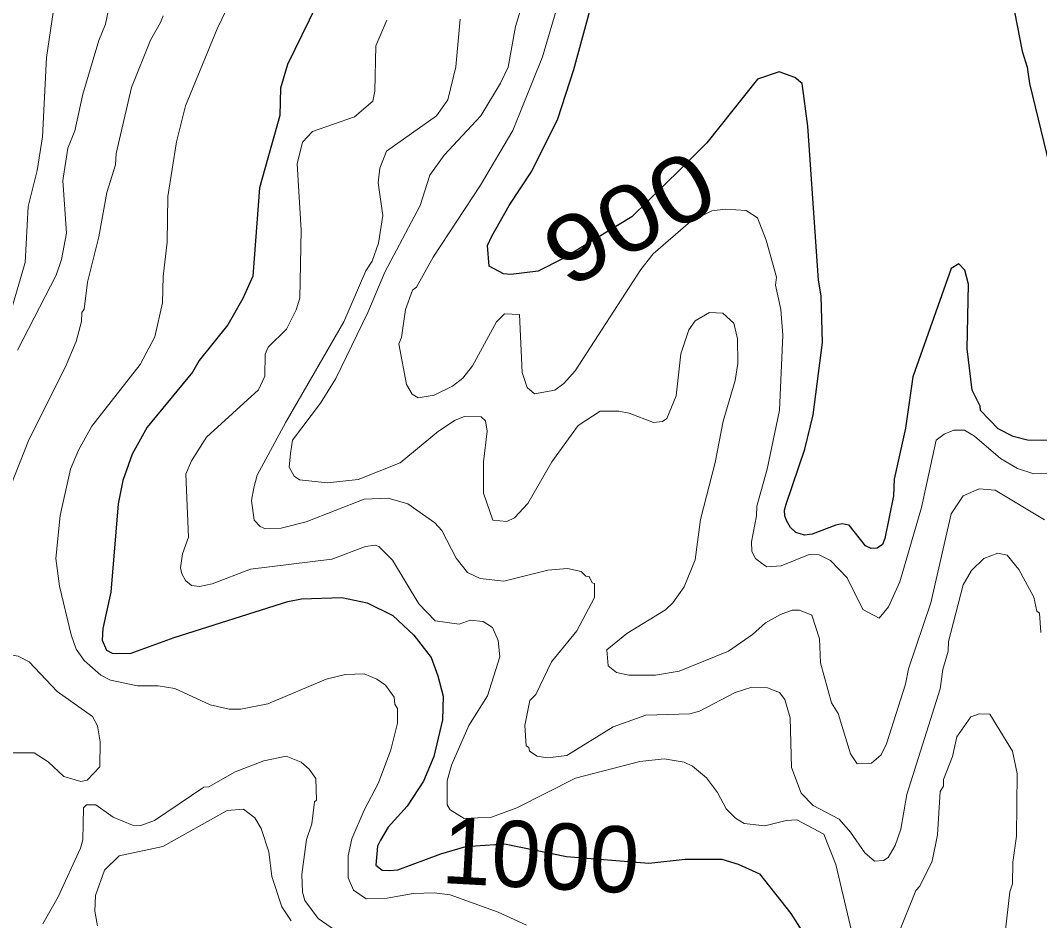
# Model space of a CAD drawing. Extents: x 598.3 to 623.2, y 6902.2 to 6930.1.
# Drawn here: x 611.773 to 613.004, y 6927.507 to 6928.595 of the extents above; entities that cross this region are included whole.
import ezdxf
from ezdxf.enums import TextEntityAlignment as Align

# ---------------------------------------------------------------- set-up
doc = ezdxf.new("R2010")
doc.units = 0
doc.header["$LTSCALE"] = 0.032
doc.layers.add('1', color=7, linetype='Continuous', lineweight=25)
doc.layers.add('2', color=7, linetype='Continuous', lineweight=13)
doc.layers.add('61', color=7, linetype='Continuous')

msp = doc.modelspace()

# ---------------------------------------------------------------- linework, layer by layer
at = {"layer": '1'}
for points in [[(613.0078, 6928.8607), (612.9766, 6928.8623), (612.9569, 6928.8518), (612.9422, 6928.8277), (612.9391, 6928.7936), (612.9472, 6928.7163), (612.9675, 6928.6366), (612.9828, 6928.5576), (612.9892, 6928.5385), (612.9917, 6928.5188), (613.0161, 6928.419)], [(612.1387, 6928.6312), (612.0954, 6928.5415), (612.0867, 6928.5129), (612.0858, 6928.4799), (612.0615, 6928.3925), (612.0534, 6928.2859), (612.0414, 6928.2587), (612.0231, 6928.227), (611.9886, 6928.1837), (611.9806, 6928.1695), (611.9257, 6928.1033), (611.9077, 6928.0706), (611.8961, 6928.0387), (611.8907, 6928.0104), (611.8818, 6927.9036), (611.8721, 6927.8598), (611.8714, 6927.8457), (611.8767, 6927.8338), (611.8833, 6927.8302), (611.9053, 6927.8295), (611.9582, 6927.8489), (612.0958, 6927.8926), (612.112, 6927.8958), (612.161, 6927.8973), (612.1914, 6927.8908)], [(612.8005, 6927.9565), (612.7936, 6927.9598), (612.7739, 6927.9847), (612.7651, 6927.9864), (612.7578, 6927.9848), (612.7294, 6927.9738), (612.7199, 6927.9728), (612.7095, 6927.976), (612.703, 6927.9821), (612.6981, 6927.9903), (612.6963, 6927.9961), (612.6958, 6928.0027), (612.6977, 6928.0102), (612.7202, 6928.0764), (612.7303, 6928.1179), (612.7416, 6928.2057), (612.7399, 6928.262), (612.7367, 6928.2808), (612.7238, 6928.467), (612.7173, 6928.5185), (612.7082, 6928.526), (612.6894, 6928.5327), (612.663, 6928.5238), (612.602, 6928.4468), (612.5707, 6928.4155), (612.5115, 6928.3576), (612.4274, 6928.3066), (612.3983, 6928.2917), (612.365, 6928.2876), (612.3564, 6928.2887), (612.3388, 6928.2978), (612.3368, 6928.3229), (612.3423, 6928.3342), (612.3631, 6928.3711), (612.3904, 6928.4125), (612.4221, 6928.4761), (612.4413, 6928.5356), (612.4641, 6928.6201)], [(613.0284, 6928.0869), (612.9895, 6928.0876), (612.9722, 6928.0919), (612.9539, 6928.1013), (612.9326, 6928.1235), (612.9322, 6928.1287), (612.9227, 6928.1479), (612.9164, 6928.1978), (612.918, 6928.2762), (612.9138, 6928.2929), (612.9066, 6928.3007), (612.8971, 6928.2949), (612.8508, 6928.1642), (612.8421, 6928.1021), (612.8282, 6928.0402), (612.8273, 6928.0201), (612.8171, 6927.9686), (612.8142, 6927.9614), (612.8077, 6927.9569), (612.8005, 6927.9565)], [(612.1914, 6927.8908), (612.2224, 6927.8757), (612.2479, 6927.8518), (612.269, 6927.8248), (612.2768, 6927.8025), (612.2833, 6927.7779), (612.2826, 6927.7496), (612.2721, 6927.705), (612.2596, 6927.6752), (612.2398, 6927.6451), (612.2168, 6927.6195), (612.2076, 6927.6041), (612.204, 6927.5965), (612.202, 6927.5736), (612.2096, 6927.5676), (612.2187, 6927.5672), (612.2285, 6927.5679), (612.2804, 6927.5874), (612.3109, 6927.5962), (612.3575, 6927.5995), (612.4323, 6927.5841), (612.532, 6927.5763), (612.5757, 6927.5809), (612.6201, 6927.5809), (612.6398, 6927.5751), (612.6654, 6927.5631), (612.7034, 6927.5153), (612.7188, 6927.491)]]:
    msp.add_lwpolyline(points, dxfattribs=at)
at = {"layer": '2'}
for points in [[(611.9217, 6928.8125), (611.8753, 6928.5904), (611.8671, 6928.5704), (611.8478, 6928.5058), (611.8383, 6928.4614), (611.8298, 6928.4405), (611.8236, 6928.4015), (611.8284, 6928.3378), (611.822, 6928.3057), (611.8158, 6928.2869), (611.7691, 6928.1963)], [(611.7602, 6928.2401), (611.7782, 6928.3021), (611.7819, 6928.3701), (611.7927, 6928.4133), (611.7992, 6928.4541), (611.8042, 6928.5501), (611.8155, 6928.6265), (611.8187, 6928.6309), (611.8188, 6928.6408), (611.8494, 6928.7685), (611.8528, 6928.7962)], [(612.4113, 6928.7208), (612.3708, 6928.5874), (612.3618, 6928.5385), (612.3528, 6928.5189), (612.329, 6928.4797), (612.2845, 6928.4321), (612.2672, 6928.408), (612.2556, 6928.3712), (612.2128, 6928.2906), (612.1924, 6928.2417), (612.1535, 6928.1622), (612.1352, 6928.1322), (612.1013, 6928.0875), (612.0989, 6928.0712), (612.0972, 6928.0547), (612.1035, 6928.0439), (612.1097, 6928.0397), (612.1435, 6928.0359), (612.1808, 6928.04), (612.2313, 6928.06), (612.2777, 6928.0984), (612.2977, 6928.1118), (612.3093, 6928.1159), (612.3294, 6928.1158), (612.3344, 6928.1109), (612.3367, 6928.0984), (612.3321, 6928.0614), (612.3321, 6928.0233), (612.3434, 6927.9907), (612.3602, 6927.989), (612.3697, 6927.9934), (612.3857, 6928.011), (612.4146, 6928.0612), (612.4466, 6928.1052), (612.4731, 6928.1224), (612.4955, 6928.1225), (612.5079, 6928.1201), (612.5375, 6928.1087)], [(612.384, 6927.5014), (612.35, 6927.5168), (612.292, 6927.538), (612.2726, 6927.5404), (612.2472, 6927.5396), (612.2156, 6927.534), (612.1903, 6927.5332), (612.1751, 6927.5436), (612.1685, 6927.5585), (612.1685, 6927.5852), (612.1731, 6927.6054), (612.188, 6927.6403), (612.2054, 6927.6734), (612.2203, 6927.7131), (612.2283, 6927.7453), (612.2283, 6927.763), (612.2251, 6927.7682), (612.2242, 6927.777), (612.2135, 6927.7913), (612.2034, 6927.7985), (612.1878, 6927.8051), (612.1655, 6927.8044), (612.1419, 6927.7984), (612.0716, 6927.7687), (612.039, 6927.7624), (612.0249, 6927.7624), (612.0017, 6927.7677), (611.9593, 6927.7874), (611.9391, 6927.7905), (611.9141, 6927.7907), (611.8812, 6927.7973), (611.8696, 6927.8033), (611.8495, 6927.8212), (611.8399, 6927.8348), (611.8337, 6927.852), (611.8197, 6927.9109), (611.8155, 6927.9443), (611.8204, 6927.9964), (611.8332, 6928.0525), (611.8428, 6928.0753), (611.859, 6928.1044), (611.9174, 6928.1791), (611.935, 6928.2125), (611.9443, 6928.2534), (611.9451, 6928.2853), (611.9498, 6928.3269), (611.9505, 6928.3822), (611.9612, 6928.4481), (611.972, 6928.4916), (612.0102, 6928.5846), (612.0274, 6928.6209)], [(612.4232, 6928.6176), (612.4035, 6928.5508), (612.3676, 6928.4619), (612.3285, 6928.3958), (612.2712, 6928.3086), (612.251, 6928.2725), (612.2461, 6928.2687), (612.238, 6928.2455), (612.2331, 6928.2116), (612.2299, 6928.204), (612.2389, 6928.1549), (612.246, 6928.1429), (612.253, 6928.1386), (612.2726, 6928.1418), (612.2946, 6928.1527), (612.307, 6928.1623), (612.3188, 6928.1773), (612.3478, 6928.2305), (612.3575, 6928.2403), (612.3757, 6928.2392), (612.3789, 6928.1692), (612.3849, 6928.151), (612.3937, 6928.1435), (612.4183, 6928.1479), (612.4292, 6928.1558), (612.443, 6928.1712), (612.522, 6928.2938), (612.5369, 6928.3127), (612.5821, 6928.3517)], [(611.9449, 6928.6003), (611.9417, 6928.5922), (611.9296, 6928.571), (611.9066, 6928.5139), (611.8884, 6928.4338), (611.8875, 6928.4204), (611.877, 6928.3869), (611.8672, 6928.3332), (611.8536, 6928.2783), (611.8494, 6928.2458), (611.8467, 6928.2418), (611.8462, 6928.231), (611.8398, 6928.2069), (611.8266, 6928.1753), (611.7828, 6928.0879), (611.7329, 6927.9621)], [(612.2152, 6928.595), (612.202, 6928.5642), (612.2007, 6928.5092), (612.1985, 6928.4971), (612.1763, 6928.4785), (612.1255, 6928.4606), (612.1135, 6928.4479), (612.1068, 6928.4216), (612.1118, 6928.3415), (612.11, 6928.2591), (612.1058, 6928.245), (612.0939, 6928.2215), (612.0717, 6928.2), (612.0681, 6928.1913), (612.068, 6928.1648), (612.0603, 6928.1484), (611.9973, 6928.0912), (611.9792, 6928.0626), (611.9726, 6928.0463), (611.9757, 6927.9703), (611.9682, 6927.9499), (611.9661, 6927.9332), (611.9677, 6927.926), (611.9722, 6927.9177), (611.9792, 6927.9118)], [(612.5932, 6927.76), (612.5815, 6927.7566), (612.5281, 6927.7549), (612.4888, 6927.741), (612.4329, 6927.7064), (612.4095, 6927.7033), (612.3971, 6927.7054), (612.3875, 6927.7117), (612.3869, 6927.7159), (612.3838, 6927.718), (612.3822, 6927.7426), (612.3879, 6927.7727), (612.3954, 6927.7801), (612.4143, 6927.8195), (612.4448, 6927.857), (612.4662, 6927.8972), (612.4662, 6927.9143), (612.4633, 6927.9152), (612.4596, 6927.9225), (612.4559, 6927.923), (612.4502, 6927.9287), (612.4334, 6927.9322), (612.4097, 6927.9305), (612.3568, 6927.9172), (612.3281, 6927.9203), (612.3126, 6927.9274), (612.2989, 6927.9449), (612.2817, 6927.9783), (612.2733, 6927.9876), (612.2407, 6928.0106), (612.2167, 6928.0172), (612.1879, 6928.0163), (612.118, 6927.9887), (612.0876, 6927.9812), (612.0688, 6927.9801), (612.0621, 6927.983), (612.0551, 6927.9908), (612.0519, 6928.0145), (612.0544, 6928.0298), (612.0586, 6928.0453), (612.0931, 6928.1094), (612.1634, 6928.2307), (612.1901, 6928.2922), (612.1976, 6928.304), (612.2054, 6928.3258), (612.2104, 6928.359), (612.2049, 6928.3986), (612.207, 6928.4161), (612.2149, 6928.4368), (612.2752, 6928.4794), (612.2889, 6928.4989), (612.2987, 6928.5386), (612.3039, 6928.5962)], [(612.5821, 6928.3517), (612.6078, 6928.3646), (612.6243, 6928.3669), (612.6494, 6928.3651), (612.663, 6928.3562), (612.6736, 6928.3294), (612.6863, 6928.2846), (612.6849, 6928.2749), (612.6913, 6928.2455), (612.6937, 6928.2142), (612.6897, 6928.1238), (612.675, 6928.0523), (612.6622, 6928.0078), (612.6621, 6927.9961), (612.6559, 6927.9647), (612.6565, 6927.953), (612.6606, 6927.9445), (612.6678, 6927.9386), (612.6744, 6927.9343), (612.6919, 6927.9356), (612.7256, 6927.9492), (612.7378, 6927.9487), (612.7512, 6927.9419), (612.7715, 6927.9209), (612.7903, 6927.8827), (612.8101, 6927.8725), (612.8215, 6927.8859), (612.8352, 6927.9162), (612.8613, 6928.0059), (612.8792, 6928.0875), (612.8889, 6928.0949), (612.9002, 6928.0997), (612.9132, 6928.0996), (612.9255, 6928.0925), (612.9569, 6928.0654), (612.9774, 6928.0531), (612.997, 6928.0467), (613.0443, 6928.0471)], [(612.5375, 6928.1087), (612.5484, 6928.1101), (612.5537, 6928.1137), (612.5649, 6928.1412), (612.5707, 6928.1918), (612.5803, 6928.221), (612.5879, 6928.2317), (612.605, 6928.2419), (612.6213, 6928.2411), (612.6347, 6928.2288), (612.6389, 6928.21), (612.6395, 6928.1801), (612.6362, 6928.1595), (612.6216, 6928.1106), (612.6119, 6928.0604), (612.5942, 6927.9916), (612.5878, 6927.943), (612.5747, 6927.9103), (612.561, 6927.8909), (612.552, 6927.8822), (612.5054, 6927.8538), (612.481, 6927.834), (612.4828, 6927.8147), (612.4927, 6927.8066), (612.5077, 6927.8035), (612.5398, 6927.8036), (612.5686, 6927.8084), (612.628, 6927.8325), (612.657, 6927.8524), (612.6728, 6927.8666), (612.6908, 6927.8769), (612.7052, 6927.8821), (612.714, 6927.882), (612.7288, 6927.8758), (612.7382, 6927.8472), (612.7391, 6927.8184), (612.7526, 6927.7701), (612.7605, 6927.7572), (612.7754, 6927.7083), (612.7834, 6927.6962), (612.8011, 6927.6971), (612.8126, 6927.7071), (612.8192, 6927.7204), (612.842, 6927.7924), (612.8458, 6927.8111), (612.8726, 6927.8909), (612.8972, 6927.9984), (612.9115, 6928.0202), (612.9312, 6928.0285), (612.9502, 6928.027), (613.0101, 6927.9913)], [(611.9792, 6927.9118), (611.989, 6927.9107), (612.0041, 6927.9138), (612.0505, 6927.9314), (612.1488, 6927.9435), (612.1897, 6927.959), (612.201, 6927.9606), (612.2056, 6927.9589), (612.222, 6927.9425), (612.2541, 6927.8898), (612.2738, 6927.8691), (612.3026, 6927.8651), (612.316, 6927.8698), (612.3317, 6927.8683), (612.343, 6927.861), (612.3498, 6927.8454), (612.352, 6927.8256), (612.3371, 6927.7786), (612.3144, 6927.7426), (612.2934, 6927.6948), (612.2883, 6927.6756), (612.2882, 6927.6467), (612.2917, 6927.6407), (612.3087, 6927.6303), (612.3419, 6927.6319), (612.3722, 6927.6431), (612.4434, 6927.6787), (612.5208, 6927.6989), (612.5505, 6927.7023), (612.5746, 6927.6983), (612.5847, 6927.6933), (612.6016, 6927.6794), (612.6149, 6927.6616), (612.6253, 6927.6419), (612.6367, 6927.6306), (612.6471, 6927.6241), (612.6722, 6927.6214), (612.6978, 6927.6278), (612.7105, 6927.6286), (612.7432, 6927.6112), (612.7579, 6927.5747), (612.7789, 6927.4857)], [(613.0055, 6927.8551), (613.0038, 6927.8785), (613.0005, 6927.8808), (612.9972, 6927.8977), (612.9788, 6927.9312), (612.9649, 6927.9483), (612.9536, 6927.9508), (612.9368, 6927.9445), (612.9217, 6927.93), (612.9116, 6927.9125), (612.8938, 6927.8443), (612.8937, 6927.8326), (612.8873, 6927.8103), (612.8838, 6927.7868), (612.8435, 6927.6591), (612.8362, 6927.6173), (612.8295, 6927.5974), (612.821, 6927.5828), (612.8156, 6927.5792), (612.8047, 6927.5785), (612.7929, 6927.5886), (612.7757, 6927.6138), (612.7617, 6927.6293), (612.7303, 6927.646), (612.7158, 6927.6609), (612.7043, 6927.6918), (612.7026, 6927.7517), (612.6962, 6927.7741), (612.6898, 6927.7824), (612.6751, 6927.7881), (612.6563, 6927.789), (612.6363, 6927.7824), (612.5932, 6927.76)], [(612.8332, 6927.4899), (612.8545, 6927.543), (612.8593, 6927.5484), (612.8743, 6927.5787), (612.8807, 6927.6106), (612.884, 6927.6626), (612.888, 6927.6692), (612.8881, 6927.6772), (612.8986, 6927.705), (612.9042, 6927.7287), (612.9211, 6927.7531), (612.931, 6927.7565), (612.9439, 6927.7564), (612.9714, 6927.7117), (612.9771, 6927.6847), (612.9762, 6927.6087), (612.9715, 6927.5774), (612.9714, 6927.551), (612.9682, 6927.5414), (612.9537, 6927.4142)], [(611.7995, 6927.503), (611.8182, 6927.5354), (611.8452, 6927.5941), (611.8478, 6927.6044), (611.8489, 6927.6432), (611.8525, 6927.6465), (611.8635, 6927.6465), (611.8846, 6927.6317), (611.908, 6927.6221), (611.9179, 6927.6215), (611.9347, 6927.6276), (611.994, 6927.668), (612.0002, 6927.6685), (612.0319, 6927.6867), (612.0667, 6927.6999), (612.0938, 6927.7056), (612.1117, 6927.6982), (612.1216, 6927.6899), (612.1295, 6927.6784), (612.1303, 6927.6524), (612.128, 6927.6502), (612.1246, 6927.6238), (612.1184, 6927.6049), (612.1125, 6927.5623), (612.1134, 6927.541), (612.1163, 6927.5309), (612.1325, 6927.5091), (612.1571, 6927.4919)], [(612.0998, 6927.5063), (612.0884, 6927.5232), (612.0763, 6927.5601), (612.0728, 6927.5898), (612.0635, 6927.618), (612.0558, 6927.631), (612.0419, 6927.6415), (612.0223, 6927.6397), (611.9446, 6927.5961), (611.892, 6927.5851), (611.8741, 6927.5675), (611.8631, 6927.5371), (611.8625, 6927.518), (611.8658, 6927.5002)]]:
    msp.add_lwpolyline(points, dxfattribs=at)
msp.add_lwpolyline([(611.8656, 6927.7421), (611.8597, 6927.7535), (611.817, 6927.7835), (611.7832, 6927.8196), (611.7699, 6927.8262), (611.7426, 6927.831), (611.7246, 6927.822), (611.7103, 6927.8116), (611.699, 6927.7827), (611.6982, 6927.7514), (611.7006, 6927.7366), (611.7037, 6927.7345), (611.7041, 6927.7304), (611.7297, 6927.7129), (611.7408, 6927.7096), (611.7892, 6927.7095), (611.8062, 6927.6986), (611.8248, 6927.6808), (611.8456, 6927.6748), (611.8533, 6927.6765), (611.8687, 6927.6926), (611.8688, 6927.7228)], close=True, dxfattribs=at)

# ---------------------------------------------------------------- texts
at = {"layer": '61', "width": 1.2}
msp.add_text('900', height=0.08, rotation=28.61, dxfattribs=at).set_placement((612.5276, 6928.3208), align=Align.CENTER)
at = {"layer": '61'}
msp.add_text('1000', height=0.08, rotation=356.906, dxfattribs=at).set_placement((612.3992, 6927.5458), align=Align.CENTER)

doc.saveas('drawing.dxf')
